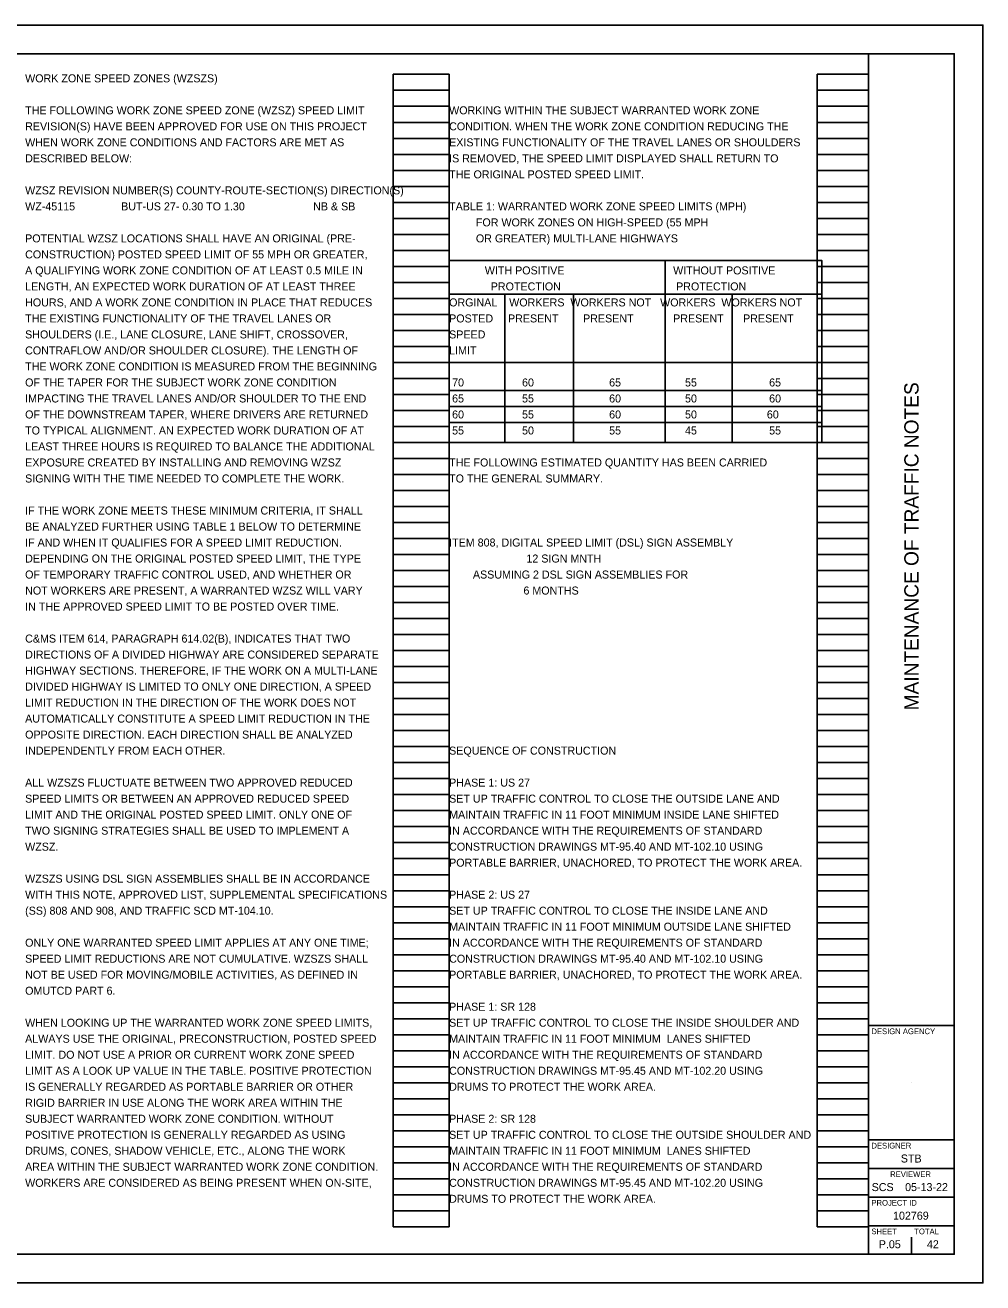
# Model space of a CAD drawing. Extents: x 0 to 86.6, y -18.4 to 22.
# Drawn here: x 17.24 to 34, y 0 to 22 of the extents above; entities that cross this region are included whole.
import ezdxf

# ---------------------------------------------------------------- set-up
doc = ezdxf.new("R2010")
doc.units = 0
for name, color, linetype in [('SH_Border', 7, 'Continuous'), ('SH_Cut_Line', 7, 'Continuous'), ('SH_Data', 7, 'Continuous'), ('SH_Text', 7, 'Continuous')]:
    doc.layers.add(name, color=color, linetype=linetype)

msp = doc.modelspace()

# ---------------------------------------------------------------- linework, layer by layer
at = {"layer": 'SH_Border'}
for p, q in [((32, 0.5), (32, 21.5)), ((32, 4.5), (33.5, 4.5)), ((32, 2.5), (33.5, 2.5)), ((32, 2), (33.5, 2)), ((32, 1.5), (33.5, 1.5)), ((32, 1), (33.5, 1))]:
    msp.add_line(p, q, dxfattribs=at)
msp.add_lwpolyline([(1.5, 21.5), (33.5, 21.5), (33.5, 0.5), (1.5, 0.5)], close=True, dxfattribs=at)
at = {"layer": 'SH_Cut_Line'}
msp.add_lwpolyline([(0, 0), (34, 0), (34, 22), (0, 22)], close=True, dxfattribs=at)
at = {"layer": 'SH_Data'}
for p, q in [((23.68, 0.98), (23.68, 21.14)), ((23.68, 21.14), (24.66, 21.14)), ((24.66, 0.98), (24.66, 21.14)), ((31.1, 0.98), (31.1, 21.14)), ((31.1, 21.14), (32, 21.14)), ((32, 0.98), (32, 21.14)), ((23.68, 20.86), (24.66, 20.86)), ((31.1, 20.86), (32, 20.86)), ((23.68, 20.58), (24.66, 20.58)), ((31.1, 20.58), (32, 20.58)), ((23.68, 20.3), (24.66, 20.3)), ((31.1, 20.3), (32, 20.3)), ((23.68, 20.02), (24.66, 20.02)), ((31.1, 20.02), (32, 20.02)), ((23.68, 19.74), (24.66, 19.74)), ((31.1, 19.74), (32, 19.74)), ((23.68, 19.46), (24.66, 19.46)), ((31.1, 19.46), (32, 19.46)), ((23.68, 19.18), (24.66, 19.18)), ((31.1, 19.18), (32, 19.18)), ((23.68, 18.9), (24.66, 18.9)), ((31.1, 18.9), (32, 18.9)), ((23.68, 18.62), (24.66, 18.62)), ((31.1, 18.62), (32, 18.62)), ((23.68, 18.34), (24.66, 18.34)), ((31.1, 18.34), (32, 18.34)), ((23.68, 18.06), (24.66, 18.06)), ((31.1, 18.06), (32, 18.06)), ((23.68, 17.78), (24.66, 17.78)), ((31.1, 17.78), (32, 17.78)), ((23.68, 17.5), (24.66, 17.5)), ((31.1, 17.5), (32, 17.5)), ((23.68, 17.22), (24.66, 17.22)), ((31.1, 17.22), (32, 17.22)), ((23.68, 16.94), (24.66, 16.94)), ((31.1, 16.94), (32, 16.94)), ((23.68, 16.66), (24.66, 16.66)), ((31.1, 16.66), (32, 16.66)), ((23.68, 16.38), (24.66, 16.38)), ((31.1, 16.38), (32, 16.38)), ((23.68, 16.1), (24.66, 16.1)), ((31.1, 16.1), (32, 16.1)), ((23.68, 15.82), (24.66, 15.82)), ((31.1, 15.82), (32, 15.82)), ((23.68, 15.54), (24.66, 15.54)), ((31.1, 15.54), (32, 15.54)), ((23.68, 15.26), (24.66, 15.26)), ((31.1, 15.26), (32, 15.26)), ((23.68, 14.98), (24.66, 14.98)), ((31.1, 14.98), (32, 14.98)), ((23.68, 14.7), (24.66, 14.7)), ((31.1, 14.7), (32, 14.7)), ((23.68, 14.42), (24.66, 14.42)), ((31.1, 14.42), (32, 14.42)), ((23.68, 14.14), (24.66, 14.14)), ((31.1, 14.14), (32, 14.14)), ((23.68, 13.86), (24.66, 13.86)), ((31.1, 13.86), (32, 13.86)), ((23.68, 13.58), (24.66, 13.58)), ((31.1, 13.58), (32, 13.58)), ((23.68, 13.3), (24.66, 13.3)), ((31.1, 13.3), (32, 13.3)), ((23.68, 13.02), (24.66, 13.02)), ((31.1, 13.02), (32, 13.02)), ((23.68, 12.74), (24.66, 12.74)), ((31.1, 12.74), (32, 12.74)), ((23.68, 12.46), (24.66, 12.46)), ((31.1, 12.46), (32, 12.46)), ((23.68, 12.18), (24.66, 12.18)), ((31.1, 12.18), (32, 12.18)), ((23.68, 11.9), (24.66, 11.9)), ((31.1, 11.9), (32, 11.9)), ((23.68, 11.62), (24.66, 11.62)), ((31.1, 11.62), (32, 11.62)), ((23.68, 11.34), (24.66, 11.34)), ((31.1, 11.34), (32, 11.34)), ((23.68, 11.06), (24.66, 11.06)), ((31.1, 11.06), (32, 11.06)), ((23.68, 10.78), (24.66, 10.78)), ((31.1, 10.78), (32, 10.78)), ((23.68, 10.5), (24.66, 10.5)), ((31.1, 10.5), (32, 10.5)), ((23.68, 10.22), (24.66, 10.22)), ((31.1, 10.22), (32, 10.22)), ((23.68, 9.94), (24.66, 9.94)), ((31.1, 9.94), (32, 9.94)), ((23.68, 9.66), (24.66, 9.66)), ((31.1, 9.66), (32, 9.66)), ((23.68, 9.38), (24.66, 9.38)), ((31.1, 9.38), (32, 9.38)), ((23.68, 9.1), (24.66, 9.1)), ((31.1, 9.1), (32, 9.1)), ((23.68, 8.82), (24.66, 8.82)), ((31.1, 8.82), (32, 8.82)), ((23.68, 8.54), (24.66, 8.54)), ((31.1, 8.54), (32, 8.54)), ((23.68, 8.26), (24.66, 8.26)), ((31.1, 8.26), (32, 8.26)), ((23.68, 7.98), (24.66, 7.98)), ((31.1, 7.98), (32, 7.98)), ((23.68, 7.7), (24.66, 7.7)), ((31.1, 7.7), (32, 7.7)), ((23.68, 7.42), (24.66, 7.42)), ((31.1, 7.42), (32, 7.42)), ((23.68, 7.14), (24.66, 7.14)), ((31.1, 7.14), (32, 7.14)), ((23.68, 6.86), (24.66, 6.86)), ((31.1, 6.86), (32, 6.86)), ((23.68, 6.58), (24.66, 6.58)), ((31.1, 6.58), (32, 6.58)), ((23.68, 6.3), (24.66, 6.3)), ((31.1, 6.3), (32, 6.3)), ((23.68, 6.02), (24.66, 6.02)), ((31.1, 6.02), (32, 6.02)), ((23.68, 5.74), (24.66, 5.74)), ((31.1, 5.74), (32, 5.74)), ((23.68, 5.46), (24.66, 5.46)), ((31.1, 5.46), (32, 5.46)), ((23.68, 5.18), (24.66, 5.18)), ((31.1, 5.18), (32, 5.18)), ((23.68, 4.9), (24.66, 4.9)), ((31.1, 4.9), (32, 4.9)), ((23.68, 4.62), (24.66, 4.62)), ((31.1, 4.62), (32, 4.62)), ((23.68, 4.34), (24.66, 4.34)), ((31.1, 4.34), (32, 4.34)), ((23.68, 4.06), (24.66, 4.06)), ((31.1, 4.06), (32, 4.06)), ((23.68, 3.78), (24.66, 3.78)), ((31.1, 3.78), (32, 3.78)), ((23.68, 3.5), (24.66, 3.5)), ((31.1, 3.5), (32, 3.5)), ((32.75, 3.5), (32.75, 3.5)), ((23.68, 3.22), (24.66, 3.22)), ((31.1, 3.22), (32, 3.22)), ((23.68, 2.94), (24.66, 2.94)), ((31.1, 2.94), (32, 2.94)), ((23.68, 2.66), (24.66, 2.66)), ((31.1, 2.66), (32, 2.66)), ((23.68, 2.38), (24.66, 2.38)), ((31.1, 2.38), (32, 2.38)), ((23.68, 2.1), (24.66, 2.1)), ((31.1, 2.1), (32, 2.1)), ((23.68, 1.82), (24.66, 1.82)), ((31.1, 1.82), (32, 1.82)), ((23.68, 1.54), (24.66, 1.54)), ((31.1, 1.54), (32, 1.54)), ((23.68, 1.26), (24.66, 1.26)), ((31.1, 1.26), (32, 1.26)), ((23.68, 0.98), (24.66, 0.98)), ((31.1, 0.98), (32, 0.98)), ((32.375, 0.675), (32.375, 0.675)), ((32.75, 0.5), (32.75, 0.8))]:
    msp.add_line(p, q, dxfattribs=at)
at = {"layer": 'SH_Text'}
for p, q in [((28.441, 17.885), (28.441, 14.7)), ((24.66, 17.292), (31.182, 17.292)), ((25.636, 17.292), (25.636, 14.7)), ((26.835, 17.292), (26.835, 14.7)), ((29.613, 17.292), (29.613, 14.7)), ((24.66, 16.1), (31.182, 16.1)), ((24.66, 15.61), (31.182, 15.61)), ((24.66, 15.332), (31.182, 15.332)), ((24.66, 15.052), (31.182, 15.052))]:
    msp.add_line(p, q, dxfattribs=at)
msp.add_lwpolyline([(24.66, 17.885), (31.182, 17.885), (31.182, 14.7), (24.66, 14.7)], close=True, dxfattribs=at)

# ---------------------------------------------------------------- texts
at = {"layer": 'SH_Data'}
msp.add_text('MAINTENANCE OF TRAFFIC NOTES', height=0.25, rotation=90, dxfattribs=at).set_placement((32.875, 10.014))
for s, height, p in [('DESIGN AGENCY', 0.1, (32.05, 4.35)), ('DESIGNER', 0.1, (32.05, 2.35)), ('STB', 0.14, (32.565, 2.105)), ('REVIEWER', 0.1, (32.378, 1.85)), ('SCS', 0.14, (32.054, 1.605)), ('05-13-22', 0.14, (32.639, 1.605)), ('PROJECT ID', 0.1, (32.05, 1.35)), ('102769', 0.14, (32.428, 1.105)), ('SHEET', 0.1, (32.05, 0.85)), ('TOTAL', 0.1, (32.8, 0.85)), ('P.05', 0.14, (32.178, 0.605)), ('42', 0.14, (33.021, 0.605))]:
    msp.add_text(s, height=height, dxfattribs=at).set_placement(p)
at = {"layer": 'SH_Text'}
for s, p in [('WORK ZONE SPEED ZONES (WZSZS)', (17.24, 21)), ('THE FOLLOWING WORK ZONE SPEED ZONE (WZSZ) SPEED LIMIT', (17.24, 20.44)), ('WORKING WITHIN THE SUBJECT WARRANTED WORK ZONE', (24.66, 20.44)), ('REVISION(S) HAVE BEEN APPROVED FOR USE ON THIS PROJECT', (17.24, 20.16)), ('CONDITION. WHEN THE WORK ZONE CONDITION REDUCING THE', (24.66, 20.16)), ('WHEN WORK ZONE CONDITIONS AND FACTORS ARE MET AS', (17.24, 19.88)), ('EXISTING FUNCTIONALITY OF THE TRAVEL LANES OR SHOULDERS', (24.66, 19.88)), ('DESCRIBED BELOW:', (17.24, 19.6)), ('IS REMOVED, THE SPEED LIMIT DISPLAYED SHALL RETURN TO', (24.66, 19.6)), ('THE ORIGINAL POSTED SPEED LIMIT.', (24.66, 19.32)), ('WZSZ REVISION NUMBER(S) COUNTY-ROUTE-SECTION(S) DIRECTION(S)', (17.24, 19.04)), ('WZ-45115', (17.24, 18.76)), ('BUT-US 27- 0.30 TO 1.30', (18.92, 18.76)), ('NB & SB', (22.28, 18.76)), ('TABLE 1: WARRANTED WORK ZONE SPEED LIMITS (MPH)', (24.66, 18.76)), ('         FOR WORK ZONES ON HIGH-SPEED (55 MPH', (24.66, 18.48)), ('POTENTIAL WZSZ LOCATIONS SHALL HAVE AN ORIGINAL (PRE-', (17.24, 18.2)), ('         OR GREATER) MULTI-LANE HIGHWAYS', (24.66, 18.2)), ('CONSTRUCTION) POSTED SPEED LIMIT OF 55 MPH OR GREATER,', (17.24, 17.92)), ('A QUALIFYING WORK ZONE CONDITION OF AT LEAST 0.5 MILE IN', (17.24, 17.64)), ('            WITH POSITIVE    ', (24.66, 17.64)), ('WITHOUT POSITIVE', (28.58, 17.64)), ('LENGTH, AN EXPECTED WORK DURATION OF AT LEAST THREE', (17.24, 17.36)), ('              PROTECTION       ', (24.66, 17.36)), (' PROTECTION', (28.58, 17.36)), ('HOURS, AND A WORK ZONE CONDITION IN PLACE THAT REDUCES', (17.24, 17.08)), ('ORGINAL    WORKERS  WORKERS NOT   WORKERS  WORKERS NOT', (24.66, 17.08)), ('THE EXISTING FUNCTIONALITY OF THE TRAVEL LANES OR', (17.24, 16.8)), ('POSTED     PRESENT  ', (24.66, 16.8)), ('  PRESENT       ', (26.9, 16.8)), ('PRESENT  ', (28.58, 16.8)), ('  PRESENT', (29.7, 16.8)), ('SHOULDERS (I.E., LANE CLOSURE, LANE SHIFT, CROSSOVER,', (17.24, 16.52)), ('SPEED', (24.66, 16.52)), ('CONTRAFLOW AND/OR SHOULDER CLOSURE). THE LENGTH OF', (17.24, 16.24)), ('LIMIT', (24.66, 16.24)), ('THE WORK ZONE CONDITION IS MEASURED FROM THE BEGINNING', (17.24, 15.96)), ('OF THE TAPER FOR THE SUBJECT WORK ZONE CONDITION', (17.24, 15.68)), (' 70        ', (24.66, 15.68)), ('   60        ', (25.78, 15.68)), ('65           ', (27.46, 15.68)), ('    55       ', (28.58, 15.68)), ('65', (30.26, 15.68)), ('IMPACTING THE TRAVEL LANES AND/OR SHOULDER TO THE END', (17.24, 15.4)), (' 65       ', (24.66, 15.4)), ('   55        ', (25.78, 15.4)), ('60          ', (27.46, 15.4)), ('    50       ', (28.58, 15.4)), ('60', (30.26, 15.4)), ('OF THE DOWNSTREAM TAPER, WHERE DRIVERS ARE RETURNED', (17.24, 15.12)), (' 60      ', (24.66, 15.12)), ('   55       ', (25.78, 15.12)), ('60     ', (27.46, 15.12)), ('    50      ', (28.58, 15.12)), ('          60', (29.7, 15.12)), ('TO TYPICAL ALIGNMENT. AN EXPECTED WORK DURATION OF AT', (17.24, 14.84)), (' 55         ', (24.66, 14.84)), ('   50        ', (25.78, 14.84)), ('55            ', (27.46, 14.84)), ('    45       ', (28.58, 14.84)), ('55', (30.26, 14.84)), ('LEAST THREE HOURS IS REQUIRED TO BALANCE THE ADDITIONAL', (17.24, 14.56)), ('EXPOSURE CREATED BY INSTALLING AND REMOVING WZSZ', (17.24, 14.28)), ('THE FOLLOWING ESTIMATED QUANTITY HAS BEEN CARRIED', (24.66, 14.28)), ('SIGNING WITH THE TIME NEEDED TO COMPLETE THE WORK.', (17.24, 14)), ('TO THE GENERAL SUMMARY.', (24.66, 14)), ('IF THE WORK ZONE MEETS THESE MINIMUM CRITERIA, IT SHALL', (17.24, 13.44)), ('BE ANALYZED FURTHER USING TABLE 1 BELOW TO DETERMINE', (17.24, 13.16)), ('IF AND WHEN IT QUALIFIES FOR A SPEED LIMIT REDUCTION.', (17.24, 12.88)), ('ITEM 808, DIGITAL SPEED LIMIT (DSL) SIGN ASSEMBLY', (24.66, 12.88)), ('DEPENDING ON THE ORIGINAL POSTED SPEED LIMIT, THE TYPE', (17.24, 12.6)), ('                          12 SIGN MNTH', (24.66, 12.6)), ('OF TEMPORARY TRAFFIC CONTROL USED, AND WHETHER OR', (17.24, 12.32)), ('        ASSUMING 2 DSL SIGN ASSEMBLIES FOR', (24.66, 12.32)), ('NOT WORKERS ARE PRESENT, A WARRANTED WZSZ WILL VARY', (17.24, 12.04)), ('                         6 MONTHS', (24.66, 12.04)), ('IN THE APPROVED SPEED LIMIT TO BE POSTED OVER TIME.', (17.24, 11.76)), ('C&MS ITEM 614, PARAGRAPH 614.02(B), INDICATES THAT TWO', (17.24, 11.2)), ('DIRECTIONS OF A DIVIDED HIGHWAY ARE CONSIDERED SEPARATE', (17.24, 10.92)), ('HIGHWAY SECTIONS. THEREFORE, IF THE WORK ON A MULTI-LANE', (17.24, 10.64)), ('DIVIDED HIGHWAY IS LIMITED TO ONLY ONE DIRECTION, A SPEED', (17.24, 10.36)), ('LIMIT REDUCTION IN THE DIRECTION OF THE WORK DOES NOT', (17.24, 10.08)), ('AUTOMATICALLY CONSTITUTE A SPEED LIMIT REDUCTION IN THE', (17.24, 9.8)), ('OPPOSITE DIRECTION. EACH DIRECTION SHALL BE ANALYZED', (17.24, 9.52)), ('INDEPENDENTLY FROM EACH OTHER.', (17.24, 9.24)), ('SEQUENCE OF CONSTRUCTION', (24.66, 9.24)), ('ALL WZSZS FLUCTUATE BETWEEN TWO APPROVED REDUCED', (17.24, 8.68)), ('PHASE 1: US 27', (24.66, 8.68)), ('SPEED LIMITS OR BETWEEN AN APPROVED REDUCED SPEED', (17.24, 8.4)), ('SET UP TRAFFIC CONTROL TO CLOSE THE OUTSIDE LANE AND', (24.66, 8.4)), ('LIMIT AND THE ORIGINAL POSTED SPEED LIMIT. ONLY ONE OF', (17.24, 8.12)), ('MAINTAIN TRAFFIC IN 11 FOOT MINIMUM INSIDE LANE SHIFTED', (24.66, 8.12)), ('TWO SIGNING STRATEGIES SHALL BE USED TO IMPLEMENT A', (17.24, 7.84)), ('IN ACCORDANCE WITH THE REQUIREMENTS OF STANDARD ', (24.66, 7.84)), ('WZSZ.', (17.24, 7.56)), ('CONSTRUCTION DRAWINGS MT-95.40 AND MT-102.10 USING ', (24.66, 7.56)), ('PORTABLE BARRIER, UNACHORED, TO PROTECT THE WORK AREA.', (24.66, 7.28)), ('WZSZS USING DSL SIGN ASSEMBLIES SHALL BE IN ACCORDANCE', (17.24, 7)), ('WITH THIS NOTE, APPROVED LIST, SUPPLEMENTAL SPECIFICATIONS', (17.24, 6.72)), ('PHASE 2: US 27', (24.66, 6.72)), ('(SS) 808 AND 908, AND TRAFFIC SCD MT-104.10.', (17.24, 6.44)), ('SET UP TRAFFIC CONTROL TO CLOSE THE INSIDE LANE AND', (24.66, 6.44)), ('MAINTAIN TRAFFIC IN 11 FOOT MINIMUM OUTSIDE LANE SHIFTED', (24.66, 6.16)), ('ONLY ONE WARRANTED SPEED LIMIT APPLIES AT ANY ONE TIME;', (17.24, 5.88)), ('IN ACCORDANCE WITH THE REQUIREMENTS OF STANDARD ', (24.66, 5.88)), ('SPEED LIMIT REDUCTIONS ARE NOT CUMULATIVE. WZSZS SHALL', (17.24, 5.6)), ('CONSTRUCTION DRAWINGS MT-95.40 AND MT-102.10 USING ', (24.66, 5.6)), ('NOT BE USED FOR MOVING/MOBILE ACTIVITIES, AS DEFINED IN', (17.24, 5.32)), ('PORTABLE BARRIER, UNACHORED, TO PROTECT THE WORK AREA.', (24.66, 5.32)), ('OMUTCD PART 6.', (17.24, 5.04)), ('PHASE 1: SR 128', (24.66, 4.76)), ('WHEN LOOKING UP THE WARRANTED WORK ZONE SPEED LIMITS,', (17.24, 4.48)), ('SET UP TRAFFIC CONTROL TO CLOSE THE INSIDE SHOULDER AND', (24.66, 4.48)), ('ALWAYS USE THE ORIGINAL, PRECONSTRUCTION, POSTED SPEED', (17.24, 4.2)), ('MAINTAIN TRAFFIC IN 11 FOOT MINIMUM  LANES SHIFTED', (24.66, 4.2)), ('LIMIT. DO NOT USE A PRIOR OR CURRENT WORK ZONE SPEED', (17.24, 3.92)), ('IN ACCORDANCE WITH THE REQUIREMENTS OF STANDARD ', (24.66, 3.92)), ('LIMIT AS A LOOK UP VALUE IN THE TABLE. POSITIVE PROTECTION', (17.24, 3.64)), ('CONSTRUCTION DRAWINGS MT-95.45 AND MT-102.20 USING ', (24.66, 3.64)), ('IS GENERALLY REGARDED AS PORTABLE BARRIER OR OTHER', (17.24, 3.36)), ('DRUMS TO PROTECT THE WORK AREA.', (24.66, 3.36)), ('RIGID BARRIER IN USE ALONG THE WORK AREA WITHIN THE', (17.24, 3.08)), ('SUBJECT WARRANTED WORK ZONE CONDITION. WITHOUT', (17.24, 2.8)), ('PHASE 2: SR 128', (24.66, 2.8)), ('POSITIVE PROTECTION IS GENERALLY REGARDED AS USING', (17.24, 2.52)), ('SET UP TRAFFIC CONTROL TO CLOSE THE OUTSIDE SHOULDER AND', (24.66, 2.52)), ('DRUMS, CONES, SHADOW VEHICLE, ETC., ALONG THE WORK', (17.24, 2.24)), ('MAINTAIN TRAFFIC IN 11 FOOT MINIMUM  LANES SHIFTED', (24.66, 2.24)), ('AREA WITHIN THE SUBJECT WARRANTED WORK ZONE CONDITION.', (17.24, 1.96)), ('IN ACCORDANCE WITH THE REQUIREMENTS OF STANDARD ', (24.66, 1.96)), ('WORKERS ARE CONSIDERED AS BEING PRESENT WHEN ON-SITE,', (17.24, 1.68)), ('CONSTRUCTION DRAWINGS MT-95.45 AND MT-102.20 USING ', (24.66, 1.68)), ('DRUMS TO PROTECT THE WORK AREA.', (24.66, 1.4))]:
    msp.add_text(s, height=0.14, dxfattribs=at).set_placement(p)

doc.saveas('drawing.dxf')
